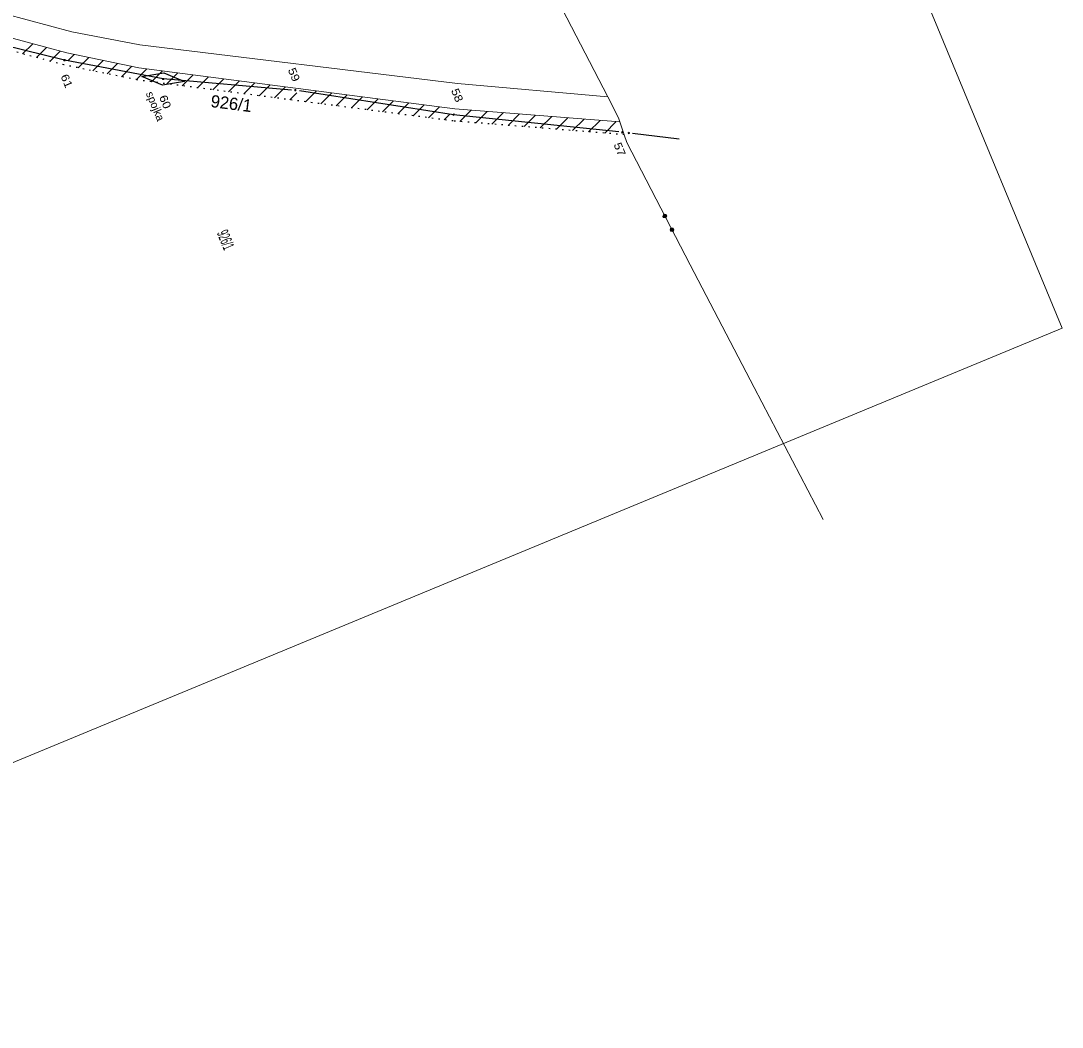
# Model space of a CAD drawing. Extents: x -687415 to -686486, y -959539 to -958099.
# Drawn here: x -686740.3 to -686486.5, y -959516.8 to -959271.3 of the extents above; entities that cross this region are included whole.
import ezdxf
from ezdxf.enums import TextEntityAlignment as Align

# ---------------------------------------------------------------- set-up
doc = ezdxf.new("R2010")
doc.units = 0
doc.header["$LTSCALE"] = 1.1
doc.linetypes.add('DOTTED', pattern=[1.5, 0.3, -1.2])
for name, color, linetype, lineweight in [('1', 7, 'Continuous', 13), ('2', 7, 'Continuous', 25), ('3', 7, 'Continuous', 13)]:
    doc.layers.add(name, color=color, linetype=linetype, lineweight=lineweight)

msp = doc.modelspace()

# ---------------------------------------------------------------- linework, layer by layer
at = {"layer": '1', "linetype": 'DOTTED', "lineweight": 25}
for p, q in [((-686729.79, -959282.07), (-686748.2, -959277.13)), ((-686711.96, -959285.74), (-686729.79, -959282.07)), ((-686634.88, -959295.75), (-686711.96, -959285.74)), ((-686593.21, -959299.09), (-686634.88, -959295.75))]:
    msp.add_line(p, q, dxfattribs=at)
at = {"layer": '1'}
for p, q in [((-686592.55, -959301.03), (-686593.21, -959299.09)), ((-686583.045, -959318.797), (-686583.578, -959319.072)), ((-686581.325, -959322.13), (-686581.859, -959322.405))]:
    msp.add_line(p, q, dxfattribs=at)
at = {"layer": '1', "lineweight": 25}
msp.add_line((-686579.835, -959300.222), (-686591.235, -959298.78), dxfattribs=at)
at = {"layer": '1'}
for points in [[(-687414.687, -958269.529), (-686898.065, -959516.766), (-686486.476, -959346.281), (-687003.099, -958099.043)], [(-686729.82, -959281.08), (-686729.82, -959280.78), (-686729.52, -959280.78), (-686729.52, -959281.08)], [(-686705.73, -959285.66), (-686705.73, -959285.36), (-686705.43, -959285.36), (-686705.43, -959285.66)], [(-686673.53, -959288.414), (-686673.53, -959288.114), (-686673.23, -959288.114), (-686673.23, -959288.414)], [(-686635.02, -959294.151), (-686634.751, -959294.019), (-686634.619, -959294.288), (-686634.888, -959294.42)], [(-686593.871, -959298.444), (-686593.602, -959298.312), (-686593.47, -959298.581), (-686593.739, -959298.713)], [(-686592.297, -959298.607), (-686592.028, -959298.475), (-686591.896, -959298.745), (-686592.165, -959298.877)], [(-686583.651, -959318.604), (-686583.384, -959318.466), (-686582.98, -959318.595), (-686582.843, -959318.862), (-686582.972, -959319.266), (-686583.238, -959319.404), (-686583.642, -959319.275), (-686583.78, -959319.008)], [(-686581.932, -959321.936), (-686581.665, -959321.799), (-686581.261, -959321.928), (-686581.123, -959322.194), (-686581.252, -959322.599), (-686581.519, -959322.736), (-686581.923, -959322.607), (-686582.061, -959322.34)]]:
    msp.add_lwpolyline(points, close=True, dxfattribs=at)
for points in [[(-686815.11, -958834.64), (-686805.51, -958854.31), (-686782.73, -958855.23), (-686777.25, -958855.45), (-686769.17, -958878.16), (-686758.67, -958907.68), (-686744.98, -958948.05), (-686719.22, -959023.5), (-686699.65, -959080.73), (-686683.05, -959115.22), (-686652.59, -959178.05), (-686618.25, -959249.24), (-686597.25, -959289.88), (-686633.86, -959286.61), (-686711.27, -959277.22), (-686727.83, -959274.04), (-686744.23, -959269.58), (-686747.57, -959266.6), (-686749.25, -959266.14)], [(-686745.48, -959274.75), (-686729.07, -959279.16), (-686711.5, -959282.77), (-686634.54, -959292.77), (-686594.27, -959295.98), (-686593.21, -959299.09)], [(-686597.25, -959289.88), (-686594.6, -959295), (-686594.27, -959295.98)], [(-686592.55, -959301.03), (-686577.18, -959330.82), (-686561.51, -959360.79), (-686544.73, -959392.97)], [(-686583.316, -959318.6), (-686583.582, -959318.737), (-686583.647, -959318.939), (-686583.113, -959318.664), (-686582.976, -959318.931), (-686583.509, -959319.206), (-686583.307, -959319.27), (-686583.04, -959319.133)], [(-686581.596, -959321.932), (-686581.863, -959322.07), (-686581.927, -959322.272), (-686581.394, -959321.997), (-686581.257, -959322.263), (-686581.79, -959322.538), (-686581.588, -959322.603), (-686581.321, -959322.465)]]:
    msp.add_lwpolyline(points, dxfattribs=at)
at = {"layer": '1', "lineweight": 25}
msp.add_lwpolyline([(-686710.798, -959284.933), (-686705.415, -959284.019), (-686700.361, -959286.086), (-686705.744, -959287)], close=True, dxfattribs=at)
at = {"layer": '2'}
for points in [[(-686674.327, -959288.232), (-686705.58, -959285.51), (-686729.67, -959280.93), (-686744.51, -959277.29), (-686747.43, -959276.25)], [(-686594.517, -959298.438), (-686634.82, -959294.22), (-686672.401, -959288.39)]]:
    msp.add_lwpolyline(points, dxfattribs=at)
at = {"layer": '3'}
for p, q in [((-686739.847, -959279.371), (-686737.398, -959276.921)), ((-686736.502, -959280.268), (-686734.054, -959277.82)), ((-686733.157, -959281.166), (-686730.71, -959278.719)), ((-686728.77, -959281.021), (-686727.277, -959279.528)), ((-686726.295, -959282.789), (-686723.757, -959280.251)), ((-686722.776, -959283.513), (-686720.238, -959280.974)), ((-686719.258, -959284.237), (-686716.718, -959281.697)), ((-686715.74, -959284.961), (-686713.199, -959282.42)), ((-686712.221, -959285.686), (-686709.557, -959283.022)), ((-686708.484, -959286.191), (-686705.803, -959283.51)), ((-686704.729, -959286.679), (-686702.048, -959283.998)), ((-686700.974, -959287.166), (-686698.293, -959284.486)), ((-686697.219, -959287.654), (-686694.538, -959284.973)), ((-686693.464, -959288.141), (-686690.784, -959285.461)), ((-686689.709, -959288.629), (-686687.029, -959285.949)), ((-686685.954, -959289.117), (-686683.274, -959286.437)), ((-686682.199, -959289.604), (-686679.519, -959286.925)), ((-686678.444, -959290.092), (-686675.765, -959287.413)), ((-686674.689, -959290.58), (-686673.009, -959288.9)), ((-686670.934, -959291.067), (-686668.255, -959288.389)), ((-686667.179, -959291.555), (-686664.5, -959288.876)), ((-686663.424, -959292.043), (-686660.746, -959289.364)), ((-686659.669, -959292.53), (-686656.991, -959289.852)), ((-686655.914, -959293.018), (-686653.236, -959290.34)), ((-686652.159, -959293.506), (-686649.481, -959290.828)), ((-686648.404, -959293.993), (-686645.726, -959291.316)), ((-686644.649, -959294.481), (-686641.972, -959291.804)), ((-686640.894, -959294.968), (-686638.217, -959292.292)), ((-686637.139, -959295.456), (-686635.848, -959294.165)), ((-686633.315, -959295.875), (-686630.529, -959293.089)), ((-686629.387, -959296.19), (-686626.6, -959293.402)), ((-686625.459, -959296.505), (-686622.67, -959293.716)), ((-686621.532, -959296.819), (-686618.741, -959294.029)), ((-686617.604, -959297.134), (-686614.812, -959294.342)), ((-686613.676, -959297.449), (-686610.882, -959294.655)), ((-686609.748, -959297.764), (-686606.953, -959294.969)), ((-686605.82, -959298.079), (-686603.023, -959295.282)), ((-686601.892, -959298.394), (-686599.094, -959295.595)), ((-686597.965, -959298.708), (-686595.164, -959295.908))]:
    msp.add_line(p, q, dxfattribs=at)

# ---------------------------------------------------------------- texts
at = {"layer": '1', "width": 1.15}
for s, p in [('59', (-686675.249, -959283.279)), ('61', (-686730.65, -959284.83)), ('58', (-686635.469, -959288.305)), ('60', (-686706.637, -959289.911)), ('57', (-686595.855, -959301.491))]:
    msp.add_text(s, height=1.95, rotation=292.5, dxfattribs=at).set_placement(p)
at = {"layer": '1'}
for s, height, rotation, p in [('spojka', 1.95, 292.5, (-686709.866, -959289.021)), ('926/1', 3, 352.8, (-686694.146, -959292.343))]:
    msp.add_text(s, height=height, rotation=rotation, dxfattribs=at).set_placement(p)
at = {"layer": '1', "width": 0.5}
msp.add_text('926/1', height=2.85, rotation=292.5, dxfattribs=at).set_placement((-686691.668, -959325.266), align=Align.CENTER)

doc.saveas('drawing.dxf')
